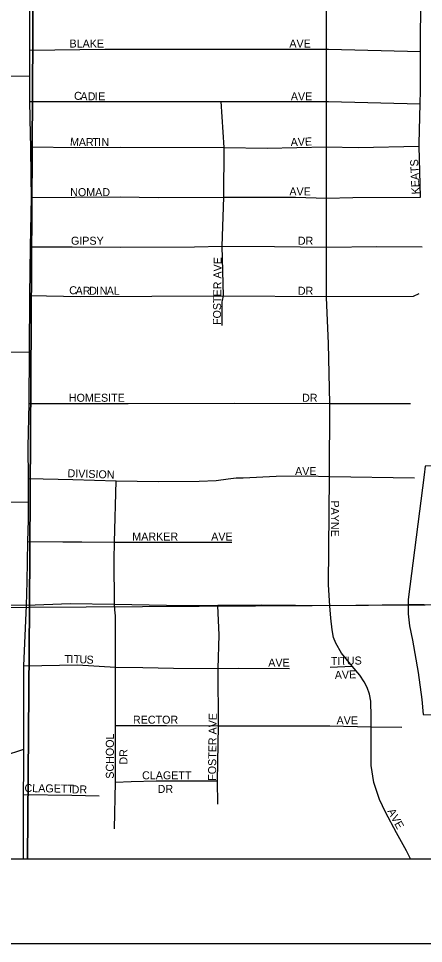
# Model space of a CAD drawing. Extents: x 8.5 to 81.5, y -1.2 to 22.4.
# Drawn here: x 52.184 to 52.663, y 14.351 to 15.445 of the extents above; entities that cross this region are included whole.
import ezdxf

# ---------------------------------------------------------------- set-up
doc = ezdxf.new("R2010")
doc.units = 0
for name, color, linetype in [('GM_X_County', 7, 'Continuous'), ('GM_X_County_Road', 7, 'Continuous'), ('GM_X_Interchange_Ramps', 7, 'Continuous'), ('GM_X_Section', 7, 'Continuous'), ('GM_X_Township', 7, 'Continuous'), ('GM_X_Township_Road', 7, 'Continuous'), ('GM_X_Township_Subdivision', 7, 'Continuous'), ('GM_X_Township_Subdivision_Text', 7, 'Continuous'), ('SH_Data', 7, 'Continuous')]:
    doc.layers.add(name, color=color, linetype=linetype)

msp = doc.modelspace()

# ---------------------------------------------------------------- linework, layer by layer
at = {"layer": 'GM_X_County'}
msp.add_lwpolyline([(54.0879, 21.2506), (49.4527, 21.2506), (49.4527, 14.4506), (56.2527, 14.4506), (56.2527, 19.1108)], dxfattribs=at)
at = {"layer": 'GM_X_County_Road'}
for points in [[(52.198, 15.4403), (52.198, 15.468), (52.198, 15.5079), (52.198, 15.5143), (52.198, 15.5342), (52.198, 15.5444), (52.198, 15.5636), (52.198, 15.6175), (52.198, 15.6459), (52.1983, 15.66)], [(52.1987, 15.3077), (52.1978, 15.3469), (52.198, 15.3591), (52.198, 15.3769), (52.198, 15.4076), (52.198, 15.4149), (52.198, 15.4403)], [(52.1945, 14.7788), (52.1955, 14.8261), (52.1961, 14.8518), (52.1964, 14.8728), (52.1962, 14.8943), (52.1962, 14.9009), (52.1957, 14.938), (52.1972, 14.9894), (52.1974, 15.0504), (52.1978, 15.1172), (52.1987, 15.1749), (52.2, 15.2331), (52.1996, 15.2581), (52.199, 15.293), (52.1987, 15.3077)], [(52.1904, 14.4872), (52.1905, 14.527), (52.1907, 14.5571), (52.1908, 14.5803), (52.1909, 14.598), (52.1909, 14.6791), (52.1939, 14.7505), (52.1945, 14.7788)], [(52.1939, 14.7505), (52.0072, 14.7513), (52.0052, 14.7513)], [(52.6645, 14.7513), (52.6451, 14.7514), (52.5526, 14.7501), (52.4715, 14.7508), (52.4201, 14.7503), (52.3798, 14.75), (52.298, 14.7516), (52.2454, 14.7524), (52.1939, 14.7505)], [(52.1903, 14.4506), (52.1903, 14.4556), (52.1904, 14.4872)]]:
    msp.add_lwpolyline(points, dxfattribs=at)
at = {"layer": 'GM_X_Interchange_Ramps'}
for points in [[(52.6785, 14.9157), (52.6654, 14.9153), (52.6643, 14.9049), (52.6452, 14.7576), (52.6451, 14.7514)], [(52.6451, 14.7514), (52.6452, 14.7405), (52.6467, 14.7264), (52.6502, 14.7094), (52.6571, 14.6711), (52.6614, 14.6393), (52.663, 14.6216), (52.678, 14.6212)]]:
    msp.add_lwpolyline(points, dxfattribs=at)
at = {"layer": 'GM_X_Section'}
for p, q in [((51.1937, 14.4506), (52.195, 14.4506)), ((52.195, 14.4506), (53.1985, 14.4506))]:
    msp.add_line(p, q, dxfattribs=at)
for points in [[(51.1955, 15.7645), (52.2033, 15.7642), (52.1975, 14.7482), (51.1961, 14.7442)], [(52.2033, 15.7642), (53.2065, 15.7628), (53.1998, 14.754), (52.1975, 14.7482)]]:
    msp.add_lwpolyline(points, close=True, dxfattribs=at)
for points in [[(53.1985, 14.4506), (53.1998, 14.754), (52.1975, 14.7482), (52.195, 14.4506)], [(52.195, 14.4506), (52.1975, 14.7482), (51.1961, 14.7442), (51.1937, 14.4506)]]:
    msp.add_lwpolyline(points, dxfattribs=at)
at = {"layer": 'GM_X_Township'}
msp.add_lwpolyline([(49.4527, 15.7601), (49.4527, 14.4506), (54.4602, 14.4506)], dxfattribs=at)
at = {"layer": 'GM_X_Township_Road'}
msp.add_lwpolyline([(51.9892, 15.3789), (51.9893, 15.3789), (52.0428, 15.3784), (52.1312, 15.3772), (52.198, 15.3769)], dxfattribs=at)
at = {"layer": 'GM_X_Township_Subdivision'}
for points in [[(52.6599, 15.2337), (52.6584, 15.2939), (52.6584, 15.2969), (52.6596, 15.3441), (52.66, 15.3598), (52.66, 15.4059), (52.66, 15.4325), (52.6606, 15.461), (52.6615, 15.5118), (52.6617, 15.5202), (52.6617, 15.5631), (52.6617, 15.593)], [(52.5488, 15.1149), (52.5488, 15.1159), (52.5487, 15.1178), (52.5487, 15.1744), (52.5487, 15.2324), (52.5487, 15.293), (52.5487, 15.3466), (52.5487, 15.4086), (52.5487, 15.4655)], [(52.198, 15.4076), (52.2864, 15.4087), (52.5487, 15.4086), (52.5509, 15.4086), (52.66, 15.4059)], [(52.1978, 15.3469), (52.2649, 15.3466), (52.4243, 15.3466), (52.5487, 15.3466), (52.5509, 15.3466), (52.6596, 15.3441)], [(52.4256, 15.1113), (52.4268, 15.1167), (52.4252, 15.1755), (52.4272, 15.2335), (52.4276, 15.2924), (52.4243, 15.3466)], [(52.199, 15.293), (52.2523, 15.2922), (52.3047, 15.2926), (52.4276, 15.2924), (52.4784, 15.2915), (52.5487, 15.293), (52.5861, 15.2922), (52.6584, 15.2939)], [(52.2, 15.2331), (52.251, 15.2337), (52.3045, 15.2339), (52.3495, 15.2331), (52.4272, 15.2335), (52.5122, 15.2337), (52.5487, 15.2324), (52.5799, 15.2333), (52.6599, 15.2337)], [(52.1987, 15.1749), (52.2481, 15.1749), (52.3046, 15.1744), (52.3925, 15.1747), (52.4252, 15.1755), (52.4873, 15.1751), (52.5487, 15.1744), (52.6081, 15.1751), (52.6617, 15.1747)], [(52.1978, 15.1172), (52.2572, 15.1161), (52.4268, 15.1167), (52.5488, 15.1159), (52.6514, 15.1166), (52.6584, 15.1198)], [(52.6482, 14.4506), (52.6433, 14.4603), (52.6316, 14.4816), (52.6183, 14.506), (52.6113, 14.521), (52.6045, 14.5409), (52.6014, 14.5613), (52.6014, 14.6069), (52.6014, 14.6189), (52.6011, 14.6374), (52.5996, 14.6456), (52.5968, 14.6535), (52.5932, 14.6603), (52.588, 14.668), (52.5789, 14.6788), (52.5664, 14.6939), (52.5596, 14.706), (52.557, 14.7127), (52.5552, 14.7218), (52.554, 14.7356), (52.5526, 14.7501), (52.5511, 14.7748), (52.5522, 14.9029), (52.5527, 14.9894), (52.5511, 15.0603), (52.5488, 15.1149)], [(52.4252, 15.0819), (52.4252, 15.1097), (52.4256, 15.1113)], [(51.9151, 14.939), (51.9318, 14.9385), (51.9476, 14.9429), (51.9594, 14.951), (51.9655, 14.9602), (51.9688, 14.974), (51.975, 14.9941), (51.9847, 15.0038), (51.9949, 15.0091), (52.0099, 15.0134), (52.0268, 15.0186), (52.0504, 15.0262), (52.0814, 15.041), (52.0973, 15.0466), (52.1161, 15.0494), (52.1341, 15.05), (52.1974, 15.0504)], [(52.1972, 14.9894), (52.3143, 14.9894), (52.4401, 14.99), (52.5527, 14.9894), (52.6479, 14.9896)], [(52.1962, 14.9009), (52.2488, 14.8994), (52.3001, 14.8979), (52.3495, 14.897), (52.398, 14.8974), (52.4181, 14.8982), (52.4322, 14.9005), (52.4417, 14.9017), (52.4498, 14.9015)], [(52.2988, 14.7411), (52.298, 14.7516), (52.2977, 14.8047), (52.2979, 14.8255), (52.3001, 14.8979)], [(52.4498, 14.9015), (52.45, 14.9015), (52.4891, 14.9033), (52.5268, 14.9037), (52.5513, 14.903)], [(52.5513, 14.903), (52.5522, 14.9029), (52.6528, 14.9014)], [(52.1964, 14.8728), (52.1322, 14.8717), (52.0677, 14.8719)], [(52.1955, 14.8261), (52.2367, 14.8257), (52.2438, 14.8258)], [(52.2438, 14.8258), (52.2594, 14.8259), (52.2979, 14.8255), (52.3421, 14.8255), (52.4368, 14.8254)], [(52.4202, 14.5156), (52.4198, 14.5431), (52.4209, 14.6082), (52.4204, 14.6759), (52.4217, 14.7155), (52.4201, 14.7503)], [(52.2981, 14.4862), (52.299, 14.5415), (52.2993, 14.6085), (52.2993, 14.6775), (52.299, 14.7389), (52.2988, 14.7411)], [(52.1909, 14.6791), (52.2541, 14.6802), (52.2993, 14.6775), (52.3314, 14.6773), (52.3678, 14.6762), (52.4204, 14.6759), (52.4451, 14.6762), (52.5051, 14.6761)], [(52.5532, 14.6774), (52.5789, 14.6788)], [(52.2993, 14.6085), (52.3593, 14.6085), (52.4209, 14.6082), (52.4963, 14.608), (52.5526, 14.6082), (52.6014, 14.6069), (52.6376, 14.6064)], [(52.1408, 14.5643), (52.1423, 14.5648), (52.1908, 14.5803)], [(52.299, 14.5415), (52.3176, 14.5424), (52.3474, 14.5431), (52.4198, 14.5431)], [(52.1905, 14.527), (52.2475, 14.5261), (52.2797, 14.5251)]]:
    msp.add_lwpolyline(points, dxfattribs=at)
at = {"layer": 'SH_Data'}
for p, q in [((49.4527, 14.4506), (56.2527, 14.4506)), ((49.3527, 14.3506), (56.3527, 14.3506))]:
    msp.add_line(p, q, dxfattribs=at)

# ---------------------------------------------------------------- texts
at = {"layer": 'GM_X_Township_Subdivision_Text'}
for s, rotation, p in [('BLAKE', 0, (52.2448, 15.4106)), ('AVE', 0, (52.5048, 15.4106)), ('C', 356.8902, (52.2499, 15.349)), ('A', 357.5608, (52.2575, 15.3485)), ('D', 359.6212, (52.2662, 15.3482)), ('I', 359.985, (52.2746, 15.3481)), ('E', 359.9956, (52.2788, 15.3481)), ('AVE', 0, (52.5065, 15.3481)), ('M', 355.6432, (52.2451, 15.2948)), ('A', 359.8237, (52.2558, 15.294)), ('R', 359.9941, (52.2642, 15.294)), ('T', 359.9956, (52.2717, 15.294)), ('I', 0, (52.2783, 15.294)), ('N', 0, (52.2825, 15.294)), ('AVE', 1.9736, (52.5064, 15.294)), ('KEATS', 92.5433, (52.6588, 15.2371)), ('NOMAD', 0, (52.2456, 15.2348)), ('AVE', 0, (52.5048, 15.2356)), ('GIPSY', 0, (52.2465, 15.1773)), ('DR', 0, (52.5148, 15.1773)), ('FOSTER AVE', 89.3383, (52.4238, 15.0823)), ('C', 356.5009, (52.2441, 15.119)), ('A', 357.6959, (52.2518, 15.1185)), ('R', 359.8516, (52.2605, 15.1181)), ('D', 359.9929, (52.268, 15.1181)), ('I', 0, (52.2763, 15.1181)), ('N', 0, (52.2805, 15.1181)), ('A', 0, (52.2888, 15.1181)), ('L', 0, (52.2972, 15.1181)), ('DR', 0, (52.5148, 15.1181)), ('HOMESITE', 0, (52.244, 14.9915)), ('DR', 0, (52.5198, 14.9915)), ('DIVISION', 358.1534, (52.2423, 14.9023)), ('AVE', 0, (52.5115, 14.9048)), ('PAYNE', 270, (52.5541, 14.8747)), ('MARKER', 0, (52.319, 14.8273)), ('AVE', 0, (52.4123, 14.8273)), ('T', 359.9454, (52.2389, 14.6823)), ('I', 359.9126, (52.2456, 14.6823)), ('T', 358.8799, (52.2497, 14.6823)), ('U', 357.4858, (52.2563, 14.6822)), ('S', 357.2672, (52.2647, 14.6818)), ('AVE', 0, (52.4798, 14.6781)), ('TITUS', 1.4681, (52.5539, 14.6798)), ('AVE', 1.9736, (52.5586, 14.6635)), ('FOSTER AVE', 89.3238, (52.418, 14.543)), ('RECTOR', 0, (52.3198, 14.6106)), ('AVE', 0, (52.5606, 14.6098)), ('SCHOOL', 90, (52.2972, 14.5455)), ('DR', 90, (52.3133, 14.5622)), ('CLAGETT', 0, (52.3306, 14.5448)), ('CLAGETT', 359.0911, (52.1915, 14.5298)), ('DR', 0, (52.2473, 14.5281)), ('DR', 0, (52.349, 14.5287)), ('AVE', 298.2998, (52.6205, 14.5072))]:
    msp.add_text(s, height=0.00947, rotation=rotation, dxfattribs=at).set_placement(p)

doc.saveas('drawing.dxf')
